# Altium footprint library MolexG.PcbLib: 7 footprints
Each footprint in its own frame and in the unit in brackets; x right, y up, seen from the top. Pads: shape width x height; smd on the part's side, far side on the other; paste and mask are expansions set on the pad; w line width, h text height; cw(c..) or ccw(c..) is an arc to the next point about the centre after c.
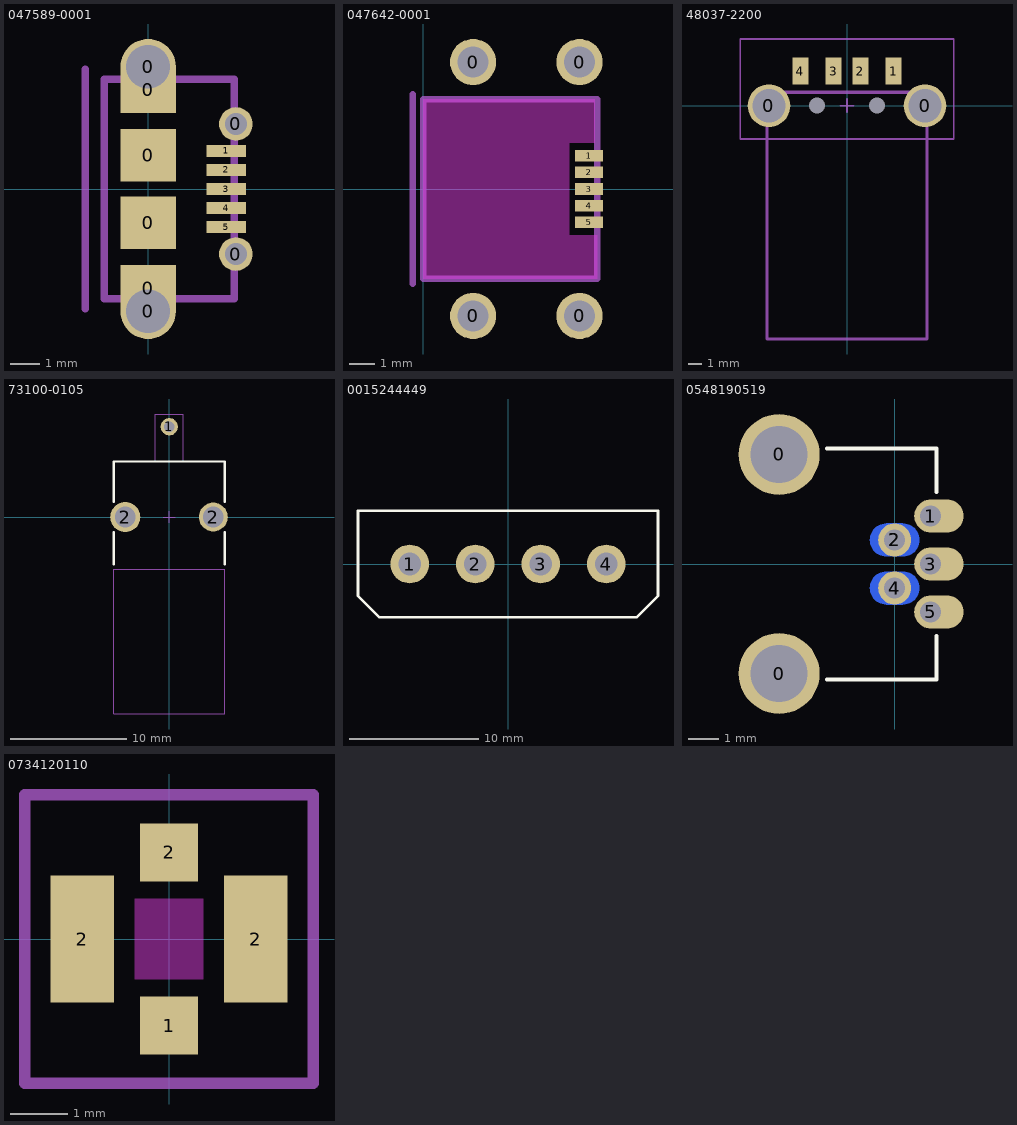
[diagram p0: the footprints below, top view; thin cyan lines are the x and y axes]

## 047589-0001 [mm] "Micro USB AB Receptacle"
height 2.5
pads (13):
  round 1.9 hole 1.5: 0(0,-4.18) 0(0,4.18)
  rect 1.9x1.6 smd: 0(0,-3.4) 0(0,3.4)
  rect 1.9x1.8 smd: 0(0,-1.15) 0(0,1.15)
  round 1.15 hole 0.75: 0(3,-2.225) 0(3,2.225)
  rect 1.35x0.4 smd: 1(2.675,1.3) 2(2.675,0.65) 3(2.675,0) 4(2.675,-0.65) 5(2.675,-1.3)
Mechanical 13:
  lines w0.254: -2.15,-4.1 -2.15,4.1 ; -1.5,-3.75 -1.5,3.75 2.95,3.75 2.95,-3.75 -1.5,-3.75
3D body: height 2.5, standoff 0, extent -1.45,-3.8 3,3.7

## 047642-0001 [mm]
pads (9):
  round 1.8 hole 1.2: 0(1.95,-4.95) 0(1.95,4.95) 0(6.1,-4.95) 0(6.1,4.95)
  rect 1.1x0.45 smd: 1(6.47,1.3) 2(6.47,0.65) 3(6.47,0) 4(6.47,-0.65) 5(6.47,-1.3)
Top Layer keep-out:
  region: 0,3.5 6.7,3.5 6.7,1.8 5.7,1.8 5.7,-1.8 6.8,-1.8 6.8,-3.5 0,-3.5
Mechanical 13:
  lines w0.254: -0.4,-3.7 -0.4,3.7 ; 0,-3.5 6.8,-3.5 6.8,3.5 0,3.5 0,-3.5
3D body: height 2.5, standoff 0, extent 0,-3.5 6.8,3.5

## 48037-2200 [mm] "USB A Type Plug SMT"
height 2.1
pads (8):
  round 3.2 hole 2.5: 0(-5.85,0) 0(5.85,0)
  round 0 hole 1.2: 0(-2.25,0) 0(2.25,0)
  rect 1.2x2 smd: 1(3.5,2.6) 2(1,2.6) 3(-1,2.6) 4(-3.5,2.6)
Mechanical 13:
  lines w0.254: -6,-2.8 -6,-17.5 6,-17.5 6,-2.8 6,1 -6,1 -6,0.9 -6,-2.7
Mechanical 15:
  lines w0.127: -0.5,0 0.5,0 ; 0,-0.5 0,0.5 ; -8,-2.5 -8,5 8,5 8,-2.5 -8,-2.5
3D body: height 2.1, standoff 0, extent -6,-17.5 6,1

## 73100-0105 [mm] "BNC Jack, right-angle"
height 8.6
pads (3):
  round 1.5 hole 0.92: 1(0,7.8)
  round 2.6 hole 1.8: 2(-3.8,0)
  round 2.5 hole 1.8: 2(3.8,0)
Top Overlay:
  lines w0.2: -4.8,-4.1 -4.8,-1.3 ; -4.8,1.3 -4.8,4.8 4.8,4.8 4.8,1.3 ; 4.8,-4.1 4.8,-1.3
Mechanical 15:
  lines w0.1: -1.2,4.8 -1.2,8.9 1.2,8.9 1.2,4.8 ; -0.5,0 0.5,0 ; 0,-0.5 0,0.5 ; -4.8,-17 -4.8,-4.5 4.8,-4.5 4.8,-17 -4.8,-17
3D body: height 8.79, standoff -0.79, extent -4.962,-17 4.6,-4
3D body: height 8.79, standoff 0.01, extent -4.365,-4 4.4,4.8

## 0015244449 [mm] "PC Power Connector, vertical"
height 10.16
pads (4):
  round 3 hole 1.778: 1(-7.62,0) 2(-2.54,0) 3(2.54,0) 4(7.62,0)
Top Overlay:
  lines w0.2: -11.63,-2.47 -9.96,-4.14 9.96,-4.14 11.63,-2.47 11.63,4.14 -11.63,4.14 -11.63,-2.47
3D body: height 10.16, standoff 0, extent -11.63,-4.14 11.63,4.14

## 0548190519 [mm] "CONN USB RECEPTACLE 5POS RT ANG"
height 4
pads (9):
  round 2.7 hole 1.9: 0(-3.85,-3.65) 0(-3.85,3.65)
  oval 1.65x1.1 hole 0.7 copper offset 0.275,0: 1(1.2,1.6) 3(1.2,0) 5(1.2,-1.6)
  round 1.1 hole 0.7: 2(0,0.8) 4(0,-0.8)
  oval 1.65x1.1 smd far side: 2(0,0.8) 4(0,-0.8)
Top Overlay:
  lines w0.127: -2.25,-3.85 1.4,-3.85 1.4,-2.4 ; -2.25,3.85 1.4,3.85 1.4,2.4
3D body: height 3.95, standoff 0, extent -7.6,-3.85 1.4,3.85

## 0734120110 [mm] "u.FL/UMCC"
height 1.3
pads (4):
  rect 1x1 smd: 1(0,-1.5) 2(0,1.5)
  rect 1.1x2.2 smd: 2(-1.5,0) 2(1.5,0)
Top Layer keep-out:
  rectangle: -0.6,-0.7 0.6,0.7
Mechanical 15:
  lines w0.2: -2.5,-2.5 2.5,-2.5 2.5,2.5 -2.5,2.5 -2.5,-2.5
3D body: height 0.36, standoff 0, extent -1.3,-1.3 1.3,1.3
3D body: height 1.3, standoff 0.36, extent -0.992,-0.998 1,0.998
